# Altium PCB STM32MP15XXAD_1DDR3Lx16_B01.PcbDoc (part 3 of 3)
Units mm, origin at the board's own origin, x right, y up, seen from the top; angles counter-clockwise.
Board outline 86 x 120 mm, 4 copper layers (Top Layer, Signal Layer 1, Signal Layer 2, Bottom Layer), stack 1.571 mm thick; 118 components, 119 nets, 781 pads, 336 vias.
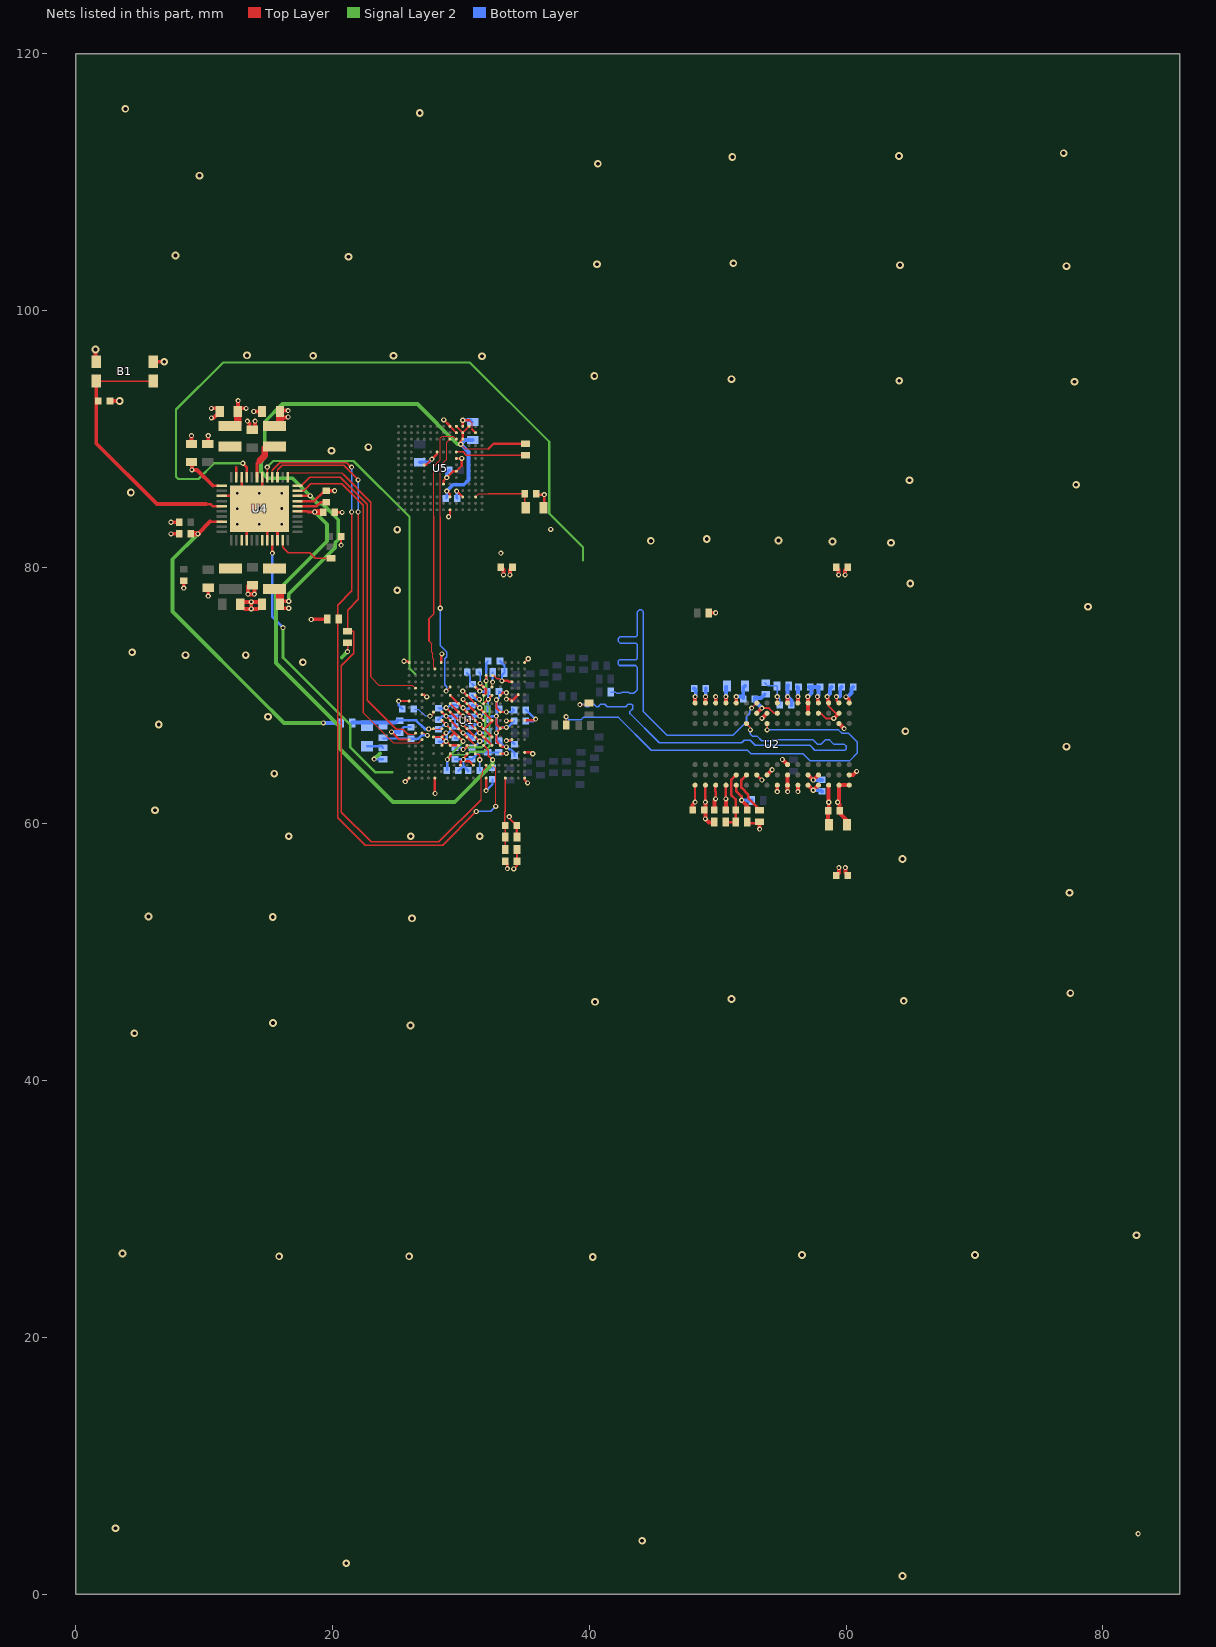
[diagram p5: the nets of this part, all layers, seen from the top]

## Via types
v1: diameter 0.4, hole 0.2, Top Layer to Bottom Layer, tented both sides, 260 vias
v2: diameter 0.6, hole 0.3, Top Layer to Bottom Layer, tented both sides, 74 vias
v3: diameter 0.4, hole 0.2, Top Layer to Signal Layer 1, tented top, 2 vias

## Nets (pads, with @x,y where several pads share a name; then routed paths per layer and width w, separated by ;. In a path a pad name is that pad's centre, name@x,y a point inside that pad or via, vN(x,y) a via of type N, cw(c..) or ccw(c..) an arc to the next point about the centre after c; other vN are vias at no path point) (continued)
GND: B1.1 B1.2 C1.1 C2.1 C3.1 C4.1 C5.1 C6.1 C7.1 C8.1 C9.1 C10.1 C11.1 C12.1 C13.1 C14.1 C15.1 C16.1 C17.1 C18.1 C19.1 C20.1 C21.1 C22.2 C23.1 C24.1 C25.1 C26.1 C27.1 C28.1 C29.1 C30.1 C31.1 C32.1 C33.1 C34.1 C35.1 C36.1 C37.1 C38.1 C39.1 C40.1 C41.1 C42.1 C43.1 C44.1 C45.1 C46.1 C47.1 C48.1 C49.1 C50.1 C51.2 C52.1 C53.1 C54.1 C55.1 C56.1 C57.1 C58.1 C59.1 C78.1 C79.1 C80.1 C81.1 C82.1 C83.1 R1.1 R14.1 R29.1 R31.1 R32.1 R33.1 R36.1 U1.1A6 U1.1B8 U1.1C3 U1.1C5 U1.1C7 U1.1D2 U1.1D4 U1.1D6 U1.1E3 U1.1E5 U1.1E7 U1.1F4 U1.1F6 U1.1G1 U1.1G2 U1.1G5 U1.1G7 U1.1H2 U1.1H3 U1.1H4 U1.1H6 U1.1H8 U1.1J5 U1.1J9 U1.A1 U1.A6 U1.A19 U1.C14 U1.D17 U1.F3 U1.F18 U1.G1 U1.G17 U1.K17 U1.K19 U1.N1 U1.N17 U1.R19 U1.U9 U1.U11 U1.W1 U1.W5 U1.W13 U1.W19 U2.A9 U2.B1 U2.B3 U2.B9 U2.D1 U2.D8 U2.E1 U2.E2 U2.E8 U2.F9 U2.G1 U2.G8 U2.G9 U2.J2 U2.J8 U2.M1 U2.M9 U2.P1 U2.P9 U2.T1 U2.T9 U4.6 U4.10 U4.15 U4.26 U4.30 U4.32 U4.41 U4.ep U5.A6 U5.C4 U5.E7 U5.G5 U5.H10 U5.J5 U5.K8 U5.N2 U5.N5 U5.P4 U5.P6 | length 145.1
  Top Layer w0.09: 30.675,91.45 30.9,91.225 30.9,90.725
  Top Layer w0.12: U1.1C5@30.51,69.34 U1.1C5@30.52,69.33 ; U1.C14@32.475,71.575 32.559,71.575 32.834,71.3 33.025,71.3 33.188,71.138 v1@33.25,71.075 ; U2.M1@51.45,69.425 U2.M1@51.45,69.525 ; v1@55.45,62.435 v1(55.45,62.525) ; U2.E8@57.05,63.825 U2.E8@57.07,63.825
  Top Layer w0.15: U1.A19@34.97,72.58 v1@35.258,72.867 ; v1@48.25,61.695 v1(48.25,61.7) U2.T9@48.25,63.025
  Top Layer w0.175: B1.1@1.55,96.05 B1.1@1.6,96 B1.1@1.6,96.25 ; C18.1@10.3,89.6 C18.1@10.325,89.625 ; C29.1@10.975,92.375 C29.1@11.225,92.125 ; C40.1@13.025,77.3 C40.1@12.825,77.1 13.175,76.75 ; C33.1@13.75,90.7 C33.1@13.975,90.925 ; C31.1@13.775,78.6 C31.1@13.925,78.45 ; 14.175,76.75 C38.1@14.525,77.1 C38.1@14.325,77.3 ; C52.1@20.175,84.275 v1(20.75,84.275) ; v1(20.675,81.725) C51.2@20.675,82.4 ; v1(24.6,67.175) 25.2,66.575 U1.N1@25.975,66.575 ; v1(25.15,69.575) U1.G1@25.975,69.575 ; v1(25.575,72.675) 25.875,72.675 U1.A1@25.975,72.575 ; v1(25.675,63.3) 25.7,63.3 U1.W1@25.975,63.575 ; U1.F3@26.975,70.075 27.175,70.075 v1(27.35,69.9) v1@27.4,69.9 ; U5.H10@27.15,87.975 27.3,87.975 v1(27.75,88.425) 28.15,88.825 U5.K8@28.15,88.975 ; U1.1G1@27.875,66.775 U1.1G2@28.525,66.775 ; v1@27.975,62.425 U1.W5@27.975,63.575 ; U1.A6@28.475,72.575 28.475,73.2 v1(28.525,73.25) ; U1.1H2@28.525,66.125 v1(28.85,66.45) ; U1.1D2@28.575,68.675 v1(28.85,68.4) U1.1E3@29.175,68.075 U1.1F4@29.825,67.425 30.162,67.088 U1.1G5@30.475,66.775 U1.1H6@31.125,66.125 ; U5.E7@28.65,86.475 28.65,86.725 v1(28.9,86.975) 29.4,87.475 U5.G5@29.65,87.475 30.075,87.9 v1(30.075,88.475) U5.J5@29.65,88.475 ; v1(28.675,91.475) 29.15,91 U5.P6@29.15,90.975 U5.N5@29.65,90.475 ; v1(28.85,67.1) U1.1G2@28.525,66.775 ; v1@28.9,66.425 v1@28.9,66.4 ; v1(29.05,83.925) 29.15,84.025 U5.A6@29.15,84.475 ; U1.1C3@29.225,69.325 U1.1D4@29.825,68.725 30.162,68.388 U1.1E5@30.475,68.075 U1.1F6@31.125,67.425 31.462,67.088 U1.1G7@31.775,66.775 U1.1H8@32.425,66.125 ; v1(29.675,85.925) 29.7,85.925 U5.C4@30.15,85.475 ; U1.1H4@29.825,66.125 U1.1H3@29.175,66.125 v1@28.9,66.4 ; U1.U9@29.975,64.575 29.975,64.825 30.188,65.038 30.2,65.05 30.212,65.038 30.367,64.883 30.668,64.883 U1.U11@30.975,64.575 ; U5.P4@30.15,90.948 U5.P4@30.15,90.975 v1(30.15,91.45) 30.675,91.45 ; v1@30.175,65.075 U1.1J5@30.525,65.425 ; v1@30.2,69.625 30.225,69.625 U1.1C5@30.475,69.375 U1.1C5@30.51,69.34 ; U1.1C5@30.52,69.33 30.825,69.025 ; 30.83,69.02 U1.1D6@31.125,68.725 31.462,68.388 U1.1E7@31.775,68.075 ; 30.9,90.725 U5.N2@31.15,90.475 ; U1.1A6@31.15,70.675 v1(31.475,70.35) ; U1.1C7@31.775,69.375 32.125,69.725 v1@32.15,69.75 ; v1(31.975,62.6) U1.W13@31.975,63.575 ; v1(32.15,69.7) v1@32.15,69.75 ; U1.1B8@32.425,70.025 v1@32.15,69.75 ; U1.1J9@33.075,65.475 33.525,65.475 v1(33.55,65.5) ; v1@33.125,81 v1(33.125,81.1) ; v1(33.2,71.15) 33.673,71.15 33.748,71.075 U1.D17@33.975,71.075 ; C9.1@33.475,57.1 33.625,56.95 v1(33.625,56.525) ; v1(33.55,68.025) 33.925,68.025 U1.K17@33.975,68.075 ; v1(33.55,69.725) 33.825,69.725 U1.G17@33.975,69.575 ; v1@33.575,66.575 33.55,66.55 33.575,66.525 33.6,66.5 33.9,66.5 U1.N17@33.975,66.575 ; v1(33.775,60.575) 33.775,60.45 C8.1@34.35,59.875 34.35,59 R36.1@34.375,58.975 ; U1.W19@34.975,63.575 34.975,63.425 v1(35.2,63.2) ; U1.K19@34.975,68.075 35.725,68.075 v1(35.825,68.175) ; C82.1@35.875,85.725 35.95,85.65 v1(36.5,85.65) 36.5,84.675 C83.1@36.45,84.625 ; U1.1G2@28.525,66.775 v1(28.85,66.45) ; v1(28.85,66.45) v1@28.9,66.4 ; v1(28.85,66.45) 28.875,66.425 v1@28.9,66.4
  Top Layer w0.2: U4.15@11.375,85.55 12.6,85.55 U4.ep@13.325,85.55 ; U4.10@12.925,87 12.925,85.95 U4.ep@13.325,85.55 ; U4.26@13.325,82.1 13.325,83.55 U4.ep@14.325,84.55 ; U4.6@14.525,87 14.525,85.75 14.525,84.75 U4.ep@14.325,84.55 ; U4.30@14.925,82.1 U4.ep@14.925,83.95 ; U4.32@15.725,82.1 15.725,83.15 U4.ep@14.925,83.95 ; U4.41@17.275,85.15 18.575,85.15 19.375,85.95 C43.1@19.525,85.95 ; U1.1D2@28.57,68.68 U1.1D2@28.575,68.675 ; U1.G17@33.975,69.575 34.46,70.06 34.46,70.075 U1.F18@34.46,70.08 ; U1.R19@34.97,65.58 34.975,65.58 35.495,65.58 v1(35.6,65.475) ; v1(49.85,61.95) 49.85,62.516 49.82,62.545 49.82,62.995 U2.P9@49.85,63.025 ; U2.M9@51.45,63.025 51.45,62.575 51.875,62.15 v1(51.875,61.85) ; R33.1@52.325,60.045 R31.1@53.13,60.045 ; R31.1@53.04,60.075 53.055,60.06 R31.1@53.13,60.045 ; R31.1@53.285,60.135 53.275,60.125 53.195,60.045 R31.1@53.13,60.045 ; v1(59.25,69.925) 59.272,69.903 59.272,69.603 U2.B1@59.45,69.425 ; U4.ep@13.325,85.55 v1(14.3,84.575) U4.ep@14.325,84.55 ; U4.ep@14.325,84.55 U4.ep@14.925,83.95
  Top Layer w0.25: v3(7.425,82.6) C49.1@8.075,82.6 ; v3(7.425,83.5) C41.1@8.075,83.5 ; v1(8.425,78.375) C32.1@8.425,78.95 ; v1(10.325,77.75) C39.1@10.325,78.4 ; C43.1@19.525,85.95 v1(20.175,85.95)
  Top Layer w0.3: B1.1@1.55,96.05 v2(1.55,96.95) ; C44.1@2.675,92.95 v2(3.425,92.95) ; B1.2@6.05,96 v2(6.9,96) ; C42.1@9.025,89.6 v1(9.025,90.25) ; C18.1@10.325,89.625 v1(10.325,90.25) ; v1(10.575,91.625) 10.725,91.625 C29.1@11.225,92.125 ; v1(10.575,92.375) C29.1@10.975,92.375 ; C40.1@13.025,77.3 v1(13.675,77.3) ; 13.175,76.75 v1(13.675,76.75) ; v1(13.375,91.375) 13.55,91.2 C33.1@13.55,90.925 ; v1(13.425,77.9) C31.1@13.425,78.55 ; v1(13.875,92.125) C34.1@14.525,92.125 ; v1(13.925,77.9) C31.1@13.925,78.45 ; C33.1@13.975,90.925 v1(13.975,91.375) ; 14.175,76.75 v1(13.675,76.75) ; C38.1@14.325,77.3 v1(13.675,77.3) ; C11.1@33.15,80 33.325,79.825 v1(33.325,79.4) ; C27.1@48.05,60.995 C27.1@48.05,61.1 48.05,61.495 v1@48.25,61.695 ; U2.T1@48.25,69.425 v1(48.25,69.925) ; R32.1@49.3,76.45 v1(49.85,76.45) ; C19.1@49.75,61.1 49.75,61.85 v1(49.85,61.95) ; U2.P1@49.85,69.425 v1(49.85,69.925) ; v1(51.45,69.925) U2.M1@51.45,69.425 U2.M1@51.455,69.43 ; v1(51.875,61.85) 52.3,61.425 C28.1@52.3,61.1 ; v1(53.275,59.6) 53.275,60.125 R31.1@53.275,60.15 ; v1(53.45,68.225) U2.J2@53.85,68.625 ; U2.J8@53.85,63.825 v1(54.25,64.225) ; v1(55.45,62.525) U2.G9@55.45,63.025 U2.G8@55.45,63.825 ; U2.G1@55.45,69.425 v1(55.45,69.925) ; v1(56.25,62.525) U2.F9@56.25,63.025 ; v1(57.025,69.925) 57.05,69.9 U2.E1@57.05,69.425 U2.E2@57.05,68.625 ; U2.E8@57.05,63.825 v1(57.45,63.425) U2.D8@57.85,63.825 ; v1@57.775,69.95 57.787,69.938 57.8,69.925 57.8,69.475 U2.D1@57.85,69.425 ; U2.B3@59.45,67.825 v1(59.85,67.425) ; C17.1@59.5,60.995 C17.1@59.5,61.025 ; v1(59.925,79.4) 59.925,79.75 60.162,79.988 C12.1@60.2,80.025 ; v1(59.95,56.6) 59.95,56.225 60.162,56.013 C10.1@60.2,55.975 ; C15.1@60.075,59.95 60.075,60.275 59.5,60.85 C17.1@59.5,61.025 ; U2.A9@60.25,63.025 U2.B9@59.45,63.025 59.45,61.795 v1(59.35,61.695) 59.5,61.545 C17.1@59.5,61.025 ; v1(13.675,76.75) v1(13.675,77.3)
  Top Layer w0.33: v1(13.425,77.9) v1(13.925,77.9)
  Bottom Layer w0.12: v1@51.875,61.875 51.887,61.863 v1@51.925,61.825 ; v1@55.42,69.955 v1(55.45,69.925)
  Bottom Layer w0.175: C2.1@25.075,67.175 C2.1@25.2,67.175 ; C2.1@25.175,67.075 25.191,67.14 C2.1@25.2,67.175 ; v1@25.175,69.575 25.175,69.225 C1.1@25.45,68.95 ; C2.1@25.25,67.125 C2.1@25.2,67.175 ; C50.1@26.125,67.55 25.575,67.55 C2.1@25.2,67.175 ; C36.1@28.25,68.125 28.525,68.4 v1(28.85,68.4) C35.1@29.55,68.4 ; C47.1@28.275,66.425 28.3,66.4 28.85,66.4 v1@28.925,66.4 ; v1@28.825,66.975 v1@28.9,67.05 ; v1@28.9,66.45 v1@28.9,67.05 ; v1@28.925,67.075 v1@28.9,67.05 ; C46.1@29.525,67.625 29.55,67.65 C35.1@29.55,68.35 C35.1@29.55,68.4 ; C4.1@29.55,65.025 29.562,65.038 29.575,65.05 v1@30.2,65.05 ; C46.1@29.55,67.6 29.625,67.6 30.15,67.075 v1@30.175,67.05 ; C46.1@29.55,67.625 29.537,67.612 28.975,67.05 v1@28.9,67.05 ; v1(29.675,85.925) 29.675,85.4 C80.1@29.725,85.35 ; C48.1@29.825,64.15 30.2,64.525 ; v1@30.2,67.05 30.525,67.05 C13.1@30.8,66.775 ; C6.1@30.475,71.75 30.725,71.5 C5.1@30.725,71.075 ; C3.1@30.575,64.15 30.563,64.163 30.2,64.525 ; C81.1@30.775,91.45 C81.1@30.925,91.3 ; C13.1@30.85,66.675 C13.1@30.875,66.7 31.275,67.1 v1(31.475,67.1) 32,67.1 C58.1@32.125,67.225 ; C5.1@30.9,70.9 31.45,70.35 v1(31.475,70.35) ; v1(31.475,68.4) 30.925,68.4 C14.1@30.875,68.35 30.825,68.4 v1(30.175,68.4) 29.552,68.4 C35.1@29.55,68.4 ; v1@31.5,68.35 31.512,68.362 C57.1@32.075,68.925 ; v1@31.5,70.3 32.05,70.3 C53.1@32.075,70.325 C53.1@32.125,70.275 ; v1(31.975,62.6) 32.475,63.1 C7.1@32.475,63.475 ; C57.1@32.075,68.95 C57.1@32.075,68.925 ; C30.1@32.1,65.625 C30.1@32.1,65.575 ; C57.1@32.15,69 C57.1@32.125,68.975 ; C53.1@32.15,70.25 C53.1@32.125,70.275 ; C45.1@33.05,72.7 33.4,72.35 R1.1@33.4,71.8 33.2,71.6 v1(33.2,71.15) ; v1(33.55,65.5) 33.025,65.5 C59.1@32.95,65.575 C30.1@32.1,65.575 ; v1(33.55,66.5) 33.9,66.5 C55.1@34.175,66.225 ; C54.1@35.05,68 35.65,68 v1(35.825,68.175) 35.8,68.175 C56.1@35.075,68.9 ; 30.2,64.525 v1(30.2,65.025) v1@30.2,65.05 ; v1@30.2,65.05 C37.1@30.875,65.05 31.4,65.575 C30.1@32.1,65.575 ; C57.1@32.075,68.925 32.087,68.937 C57.1@32.125,68.975 ; C57.1@32.125,68.975 32.125,69.7 C53.1@32.125,70.275
  Bottom Layer w0.3: v1(24.6,67.175) C2.1@25.2,67.175 ; C79.1@26.8,88.175 27.5,88.175 v1(27.75,88.425) ; v1(28.9,86.975) 28.9,87.35 C78.1@29.1,87.55 ; v1(30.15,91.45) C81.1@30.775,91.45 ; C24.1@48.175,70.55 48.3,70.425 48.3,70 v1@48.25,69.95 ; v1(51.45,69.925) 51.875,69.925 52,69.8 52,70.625 C16.1@52.125,70.75 ; v1@51.925,61.825 R14.1@52.65,61.825 ; R29.1@55.475,70.775 55.45,70.75 v1(55.45,69.925) 55.75,69.625 C26.1@55.75,69.275 C26.1@55.75,69.25 ; v1(57.025,69.925) 57.3,70.2 57.3,70.475 57.15,70.625 57.1,70.675 C23.1@57.2,70.675 C21.1@57.85,70.675 ; v1(57.45,63.425) 57.46,63.435 C22.2@58.13,63.435 ; v1(57.775,69.925) 57.85,70 C21.1@57.85,70.675 ; C21.1@57.86,70.685 C21.1@57.85,70.675 ; C21.1@57.9,70.675 C21.1@57.85,70.675 ; v1@59.39,69.925 59.5,69.925 59.55,69.975 59.55,70.575 C20.1@59.65,70.675
  other v1: 82.75,4.725 28,62.375 30.175,67.1 30.175,69.7 35.25,72.875 37,82.95 12.6,83.35 14.3,83.35 16.05,83.35 12.575,84.55 16.05,84.575 12.6,85.75 14.3,85.75 16.05,85.75
  other v2: 64.4,1.425 21.075,2.425 44.125,4.175 3.1,5.15 40.275,26.275 15.85,26.325 25.975,26.325 56.575,26.425 70.05,26.425 3.65,26.55 82.625,27.975 4.575,43.7 26.075,44.3 15.375,44.5 40.45,46.15 64.5,46.225 51.075,46.375 77.475,46.825 26.2,52.65 15.35,52.75 5.675,52.8 77.4,54.65 64.4,57.275 16.6,59.05 26.1,59.05 31.475,59.05 6.175,61.075 15.475,63.925 77.175,66.025 64.625,67.225 6.475,67.75 14.975,68.35 17.7,72.6 8.55,73.15 13.25,73.15 4.4,73.375 78.85,76.925 25.05,78.2 65,78.725 63.5,81.9 58.95,82 44.8,82.05 54.75,82.075 49.15,82.2 25.05,82.925 4.3,85.825 77.925,86.425 64.95,86.775 19.925,89.075 22.8,89.35 77.8,94.45 64.15,94.525 51.075,94.65 40.4,94.9 31.65,96.425 18.5,96.475 24.75,96.475 13.35,96.5 77.175,103.45 64.2,103.525 40.6,103.6 51.225,103.675 21.25,104.175 7.775,104.275 9.65,110.5 40.675,111.425 51.15,111.95 64.125,112.025 76.95,112.25 26.8,115.375 3.875,115.7
I2C4_SCL: R37.2 U1.U14 U4.4 | length 52.6
  Top Layer w0.09: 15.3,87.54 15.3,87.025 U4.4@15.325,87 ; U1.U14@32.475,64.575 32.72,64.33 v1@32.72,61.425
  Top Layer w0.1: 15.3,87.54 15.885,88.125 21.1,88.125 21.425,87.8 v1(21.5,87.8) ; v1(21.5,84.3) 21.5,78.15 20.4,77.05 20.4,75.95 20.4,60.5 22.55,58.35 28.575,58.35 v1(31.2,60.975)
  Bottom Layer w0.1: v1(21.5,84.3) v1(21.5,87.8) ; v1(31.2,60.975) 32.325,60.975 v1(32.725,61.375)
I2C4_SDA: R38.2 U1.U13 U4.3 | length 50.6
  Top Layer w0.09: U4.3@15.725,87 15.725,87.575 ; 31.575,61.9 31.575,63.762 31.72,63.907 31.72,64.166 31.975,64.421 U1.U13@31.975,64.575
  Top Layer w0.1: 15.725,87.575 16.075,87.925 20.875,87.925 v1(22,86.8) ; v1@22.025,84.275 22.025,77.5 21.175,76.65 R38.2@21.175,75 21.675,75 21.675,73.3 20.7,72.325 20.7,60.925 23.025,58.6 28.275,58.6 31.575,61.9
  Bottom Layer w0.1: v1(22,84.3) v1(22,86.8)
NetB1_3: B1.3 B1.4 C44.2 U4.17 | length 21.5
  Top Layer w0.1: B1.3@1.325,94.775 B1.3@1.6,94.5 B1.4@6.05,94.5
  Top Layer w0.2: 10.125,84.9 10.525,84.9 10.675,84.75 U4.17@11.375,84.75
  Top Layer w0.3: B1.3@1.6,94.45 1.6,92.95 1.6,89.65 6.325,84.925 10.15,84.925
NetC1_2: C1.2 U1.1D1 | length 1.9
  Top Layer w0.09: v1(27.6,68.4) 27.65,68.4 27.925,68.675 U1.1D1@27.925,68.65
  Bottom Layer w0.09: C1.2@26.375,68.95 26.7,68.95 27.225,68.425 27.55,68.425 27.587,68.388 v1@27.6,68.375
NetC2_2: C2.2 L5.2 R41.1 R42.2 U1.1F1 U1.1F2 | length 7.4
  Top Layer w0.09: v1@27.5,67.375 27.875,67.375 28.525,67.375 U1.1F2@28.575,67.375
  Bottom Layer w0.2: C2.2@25.075,68.075 25.25,68.075 26.525,68.075 27.2,67.4 v1(27.5,67.4)
  Bottom Layer w0.3: R42.2@21.55,67.9 22.7,67.9 23.925,67.9 24.9,67.9 C2.2@25.075,68.075
NetC3_2: C3.2 U1.1J6 | length 1.7
  Top Layer w0.09: v1@31.5,65 v1@31.5,65.1
  Top Layer w0.1: U1.1J6@31.175,65.425 31.4,65.425 31.475,65.35 v1(31.475,65) v1@31.5,65
  Bottom Layer w0.1: C3.2@31.475,64.175 v1(31.475,65)
  Bottom Layer w0.175: C3.2@31.5,64.2 C3.2@31.525,64.175
NetC6_2: C6.2 U1.1A7 U1.1B7 | length 2.1
  Top Layer w0.2: v1(31.5,70.95) U1.1A7@31.775,70.675 31.95,70.5 31.95,70.2 U1.1B7@31.775,70.025
  Bottom Layer w0.1: C6.2@31.4,71.85 31.5,71.75 v1(31.5,70.95)
NetC8_2: C8.2 R35.1 R36.2 U1.W16 | length 5.6
  Top Layer w0.1: R35.1@33.475,58 33.45,58.025 33.45,58.975 C8.2@33.45,59.875 33.425,59.9 33.425,60.95 33.475,61 U1.W16@33.475,63.575
NetC26_2: C26.2 R28.1 R29.2 U2.H1 | length 3.1
  Top Layer w0.12: U2.H1@54.65,69.39 U2.H1@54.65,69.425 v1@54.65,69.905
  Bottom Layer w0.1: R29.2@54.575,70.75 54.6,70.725 R29.2@54.65,70.675
  Bottom Layer w0.12: R28.1@53.675,71 53.712,70.963 53.925,70.75 R29.2@54.575,70.75 ; R29.2@54.65,70.675 v1(54.65,69.925) 54.85,69.725 C26.2@54.85,69.275
NetC28_2: C28.2 R30.1 R33.2 U2.M8 | length 4.8
  Top Layer w0.1: R30.1@50.625,60.15 R30.1@50.65,60.15 ; R33.2@51.41,60.165 R33.2@51.425,60.15
  Top Layer w0.12: 51.413,61.913 51.425,61.9
  Top Layer w0.2: R30.1@50.65,60.15 R33.2@51.425,60.15 ; R33.2@51.41,60.165 C28.2@51.41,61.1 51.425,61.115 51.425,61.9 ; 51.413,61.913 51.05,62.275 51.05,63.425 U2.M8@51.45,63.825
NetC43_2: C43.2 U4.40 | length 2.4
  Top Layer w0.2: U4.40@17.275,84.75 18.775,84.75 19.075,85.05 C43.2@19.525,85.05
NetC82_2: C82.2 C83.2 U5.C2 | length 5.1
  Top Layer w0.09: U5.C2@31.15,85.475 31.4,85.725 32.15,85.725
  Top Layer w0.1: 32.15,85.725 C82.2@34.975,85.725 34.975,84.7 C83.2@35.05,84.625
NetL1_1: L1.1 U4.7 | length 3.2
  Top Layer w0.2: U4.7@14.125,87 14.125,88.1 14.325,88.3
  Top Layer w0.5: 14.325,88.3 14.725,88.7 14.725,89.3 14.825,89.4 L1.1@15.325,89.4
NetL2_1: L2.1 U4.11 | length 0.8
  Top Layer w0.2: U4.11@12.525,87 12.525,87.8
NetL3_1: L3.1 U4.29
NetL4_1: L4.1 U4.25
NetL5_1: L5.1 R39.2 | length 1.3
  Bottom Layer w0.2: L5.1@22.7,66.05 23.825,66.05 R39.2@23.925,65.95
NetR1_2: R1.2 U1.1A8 | length 1.2
  Top Layer w0.09: U1.1A8@32.425,70.675 32.425,71 v1(32.475,71.05)
  Bottom Layer w0.1: R1.2@32.475,71.775 R1.2@32.5,71.8
  Bottom Layer w0.175: v1(32.475,71.05) R1.2@32.475,71.775
NetR31_2: R31.2 U2.L8 | length 3.5
  Top Layer w0.2: U2.L8@52.25,63.825 51.85,63.425 51.85,62.825 52.4,62.275 52.4,61.995 53.26,61.135 R31.2@53.26,61.075 R31.2@53.26,61.055
NetR40_1: R40.1 U5.K5 | length 5.5
  Top Layer w0.1: U5.K5@29.65,88.975 30.175,88.975 30.42,88.73 31.98,88.73 31.985,88.725 R40.1@35.025,88.725
NetR43_1: R43.1 U4.33 | length 4.7
  Top Layer w0.1: U4.33@16.125,82.1 16.125,81.55 16.55,81.125 18.25,81.125 18.675,80.7 R43.1@19.9,80.7
NRST: U1.E2 U4.1 | length 25.2
  Top Layer w0.09: U4.1@16.525,87 16.525,87.35 20.725,87.35 20.85,87.225 ; 23,71.45 23.625,70.825 26.225,70.825 U1.E2@26.475,70.575
  Top Layer w0.1: 20.85,87.225 23,85.075 23,71.45
ODT: R27.2 U2.K1 | length 33.2
  Top Layer w0.12: v1(52.65,69.025) U2.K1@53.05,69.425
  Bottom Layer w0.12: R27.2@41.675,70.275 42.05,70.275 42.155,70.17 42.445,70.17 42.55,70.275 43.05,70.275 43.15,70.175 43.475,70.175 43.725,70.425 43.725,72.225 43.605,72.345 42.355,72.345 42.245,72.455 42.245,72.695 42.35,72.8 43.65,72.8 43.725,72.875 43.725,74 43.63,74.095 42.4,74.095 42.245,74.25 42.245,74.42 42.4,74.575 43.625,74.575 43.725,74.675 43.725,76.5 43.9,76.675 44.075,76.675 44.225,76.525 44.225,68.75 46,66.975 46.07,66.905 51.2,66.905 52.14,67.845 52.14,67.851 52.25,67.961 52.25,68.334 52.5,68.584 52.5,68.814 52.65,68.964 v1(52.65,69.025)
PA0_WKUP: U1.N3 U4.43 | length 27.8
  Top Layer w0.09: 22.4,68.675 24.75,66.325 26.725,66.325 U1.N3@26.975,66.575
  Top Layer w0.1: 17.775,85.95 18.325,86.5 20.725,86.5 22.4,84.825 22.4,68.675
  Top Layer w0.12: U4.43@17.275,85.95 17.775,85.95
PWR_ON: U1.M2 U4.44 | length 26.4
  Top Layer w0.09: 26.05,66.99 26.39,66.99 U1.M2@26.475,67.075
  Top Layer w0.1: U4.44@17.575,86.35 18.225,87 20.625,87 22.725,84.9 22.725,69.625 24.957,67.392 25.465,67.392 25.853,67.005 26.05,67.005
RASN: R22.2 U2.J3 | length 34
  Top Layer w0.09: v1(38.2,68.35) 38.2,67.7 38.212,67.688 R22.2@38.225,67.675
  Top Layer w0.12: v1(53.85,67.325) U2.J3@53.85,67.825
  Bottom Layer w0.12: v1(38.2,68.35) 38.44,68.11 39.355,68.11 39.545,68.3 42.281,68.3 44.836,65.745 52.32,65.745 52.58,65.485 56.64,65.485 57.215,64.91 60.273,64.91 60.865,65.502 60.865,66.404 60.199,67.07 60.004,67.07 59.999,67.065 59.685,67.065 59.425,67.325 v1(53.85,67.325) v1@53.875,67.35
SDMMC2_CK: U1.1A3 U5.M6 | length 20.8
  Top Layer w0.09: 28.4,83.925 28.4,87.9 28.9,88.4 28.9,89.725 U5.M6@29.15,89.975 ; v1(28.85,70.35) U1.1A3@29.175,70.675 ; v1@28.888,70.287 v1@28.9,70.3
  Top Layer w0.13: v1(28.4,76.8) 28.4,83.925
  Bottom Layer w0.1: 28.75,71.7 28.75,70.853 28.9,70.703 28.9,70.35 v1@28.9,70.275
  Bottom Layer w0.13: v1(28.4,76.8) 28.4,73.9 28.9,73.4 28.9,73.025 28.75,72.875 28.75,71.7
SDMMC2_CMD: U1.B5 U5.M5 | length 20
  Top Layer w0.09: 27.525,74.25 27.753,74.022 27.753,73.378 27.822,73.31 27.822,72.914 27.89,72.845 27.89,72.21 U1.B5@27.975,72.125 ; 27.9,83.975 27.9,87.875 28.4,88.375 28.4,90.064 28.551,90.215 29.41,90.215 U5.M5@29.65,89.975 ; U1.B5@27.975,72.075 U1.B5@27.975,72.125 ; U1.B5@27.975,72.145 U1.B5@27.975,72.125
  Top Layer w0.13: 27.525,74.25 27.525,75.975 27.9,76.35 27.9,83.975
VDD: C38.2 C45.2 C46.2 C47.2 C48.2 C80.2 C81.2 L3.2 R37.1 R38.1 R39.1 R40.2 U1.1E2 U1.1F3 U1.1G3 U1.1G4 U1.1J3 U1.C13 U4.31 U4.42 U5.C6 U5.M4 U5.N4 U5.P3 U5.P5 | length 102.2
  Top Layer w0.09: C38.2@16.175,77.35 C38.2@15.925,77.1 C38.2@16.225,76.8 ; v1(18.35,75.925) v1@18.375,75.95 ; v1(30,89.575) 30.35,89.225 32.15,89.225
  Top Layer w0.1: v1(21.175,73.425) R38.1@21.175,74.1
  Top Layer w0.175: U1.1E2@28.525,68.075 v1(28.85,67.75) U1.1F3@29.175,67.425 29.5,67.1 ; v1(28.9,85.925) 29.15,85.675 U5.C6@29.15,85.475 ; v1(28.95,65.025) 29.225,65.3 U1.1J3@29.225,65.425 ; U1.1G3@29.175,66.775 29.5,67.1 ; U5.P5@29.65,90.975 U5.N4@30.15,90.475 ; v1(30,89.575) 30,89.825 U5.M4@30.15,89.975 U5.N4@30.15,90.475 ; v1@30.2,66.42 30.172,66.447 29.845,66.775 U1.1G4@29.825,66.775 29.5,67.1 ; U5.P3@30.65,90.975 U5.N4@30.15,90.475 ; v1(31.975,71.15) U1.C13@31.975,71.575 ; 32.15,89.225 32.55,89.625 R40.2@35.025,89.625
  Top Layer w0.2: v1(15.325,81.1) U4.31@15.325,82.1 ; U4.42@17.275,85.55 v1(18.275,85.55)
  Top Layer w0.3: C38.2@16.175,77.35 v1(16.6,77.35) ; C38.2@16.225,76.8 v1(16.6,76.8) ; v1@18.375,75.95 R37.1@19.6,75.95
  Top Layer w0.6: C38.2@15.925,77.1 L3.2@15.925,78.3
  Signal Layer 2 w0.09: 31.803,69.948 31.803,69.56 32.225,69.137 32.225,69
  Signal Layer 2 w0.1: v1(28.95,65.025) v1@28.975,65.05 ; 29.2,65.4 30.525,65.4
  Signal Layer 2 w0.175: v1@28.9,67.7 30.162,66.437 v1@30.2,66.4 ; v1@28.975,65.025 28.975,65.05 28.975,65.175 29.2,65.4 v1@30.2,66.4 ; v1@30.25,66.35 v1@30.2,66.4 ; 30.525,65.425 30.73,65.63 31.805,65.63 32.225,66.05 32.225,69 ; 31.803,69.948 31.975,70.12 v1(31.975,71.15)
  Signal Layer 2 w0.2: v1(16.15,75.3) 16.15,72.95 21.4,67.7 21.4,65.975 23.35,64.025 24.675,64.025
  Signal Layer 2 w0.3: v1(16.6,77.35) 16.6,77.914 20.225,81.539 20.225,81.911 20.45,82.136 20.45,83.7 19.175,84.975 18.85,84.975 v1(18.275,85.55) 16.9,86.925 14.95,86.925 14.425,87.45 14.425,88.2 14.725,88.5 14.725,91.325 16.1,92.7 26.625,92.7 29.75,89.575 v1(30,89.575) ; 20.725,72.975 v1(21.175,73.425) ; v1(23.25,65.05) 23.7,65.5
  Bottom Layer w0.1: C80.2@28.825,85.35 C80.2@28.9,85.425 ; C45.2@31.975,72.525 C45.2@32.15,72.7
  Bottom Layer w0.175: v1(23.25,65.05) R39.1@23.925,65.05 ; C47.2@28.3,67.375 28.625,67.7 28.85,67.7 v1@28.9,67.7 ; C80.2@28.9,85.425 v1(28.9,85.925) ; C48.2@28.925,64.2 28.95,64.225 v1(28.95,65.025) ; C46.2@29.55,66.675 29.925,66.675 30.162,66.437 v1@30.2,66.4 ; v1(31.975,71.15) C45.2@31.975,72.525
  Bottom Layer w0.2: v1(15.325,81.1) 15.325,76.125 v1(16.15,75.3)
  Bottom Layer w0.3: v1(28.9,85.925) 29.4,86.425 30.225,86.425 30.6,86.8 30.6,88.975 v1(30,89.575) 30.325,89.9 C81.2@30.925,89.9
  other v1: 30.175,66.45
VDD_CORE: C13.2 C14.2 C30.2 C34.2 C35.2 C36.2 C37.2 L1.2 U1.1B3 U1.1B5 U1.1C4 U1.1C6 U1.1D3 U1.1D5 U1.1D7 U1.1E4 U1.1E6 U1.1E8 U1.1F5 U1.1F7 U1.1G6 U1.1G8 U4.5 | length 48.1
  Top Layer w0.15: U4.5@14.925,87 v1(14.925,87.8)
  Top Layer w0.175: C34.2@15.925,92.125 C34.2@16,92.2 ; v1@16.5,91.65 v1(16.55,91.7) ; v1@28.9,69 U1.1D3@29.175,68.725 U1.1E4@29.825,68.075 30.162,67.738 U1.1F5@30.475,67.425 U1.1G6@31.125,66.775 31.175,66.725 v1@31.462,66.437 ; U1.1B3@29.225,69.975 U1.1C4@29.825,69.375 30.162,69.038 U1.1D5@30.475,68.725 U1.1E6@31.125,68.075 31.462,67.738 U1.1F7@31.775,67.425 U1.1F7@31.825,67.375 ; v1@30.188,70.313 U1.1B5@30.475,70.025 U1.1C6@31.125,69.375 31.462,69.038 U1.1D7@31.775,68.725 31.825,68.675 U1.1E8@32.425,68.075 32.475,68.025 U1.1F7@31.825,67.375 ; U1.1G8@32.425,66.775 U1.1F7@31.825,67.375
  Top Layer w0.3: 15.925,91.65 v1@16.5,91.65 ; C34.2@16,92.2 v1(16.55,92.2)
  Top Layer w0.6: L1.2@15.325,91 L1.2@15.475,91 15.725,91 15.925,91.2 15.925,91.65 C34.2@15.925,92.1
  Signal Layer 2 w0.175: v1(14.925,87.8) 15.4,88.275 21.65,88.275 26,83.925 26,72.125 26.45,71.675
  Bottom Layer w0.175: C36.2@28.3,69.025 28.325,69 28.85,69 28.9,69 29.15,69.25 C35.2@29.55,69.25 29.925,69.25 30.15,69.025 v1@30.225,68.95 ; v1(30.175,67.75) 30.725,67.75 C13.2@30.875,67.6 31.025,67.75 v1(31.475,67.75) ; v1@30.2,68.975 30.625,68.975 30.887,69.237 C14.2@30.9,69.25 ; C37.2@30.875,65.95 31.025,65.95 31.475,66.4 v1(31.475,66.45) ; C14.2@30.875,69.25 C14.2@30.9,69.25 ; v1@31.475,66.475 C30.2@32.1,66.475 ; v1@31.525,69.025 31.487,69.063 31.3,69.25 C14.2@30.9,69.25
  other v1: 28.85,69.05 30.175,69.05 31.475,69.05 30.15,70.35
VDD_DDR: C9.2 C10.2 C11.2 C12.2 C15.2 C16.2 C17.2 C19.2 C20.2 C21.2 C22.1 C23.2 C24.2 C25.2 C27.2 C29.2 C42.2 C53.2 C54.2 C55.2 C56.2 C57.2 C58.2 C59.2 L2.2 R28.2 R30.2 R35.2 U1.1B9 U1.1D9 U1.1F9 U1.1H9 U2.A1 U2.A8 U2.B2 U2.C1 U2.C9 U2.D2 U2.D9 U2.E9 U2.F1 U2.G7 U2.H2 U2.H9 U2.K2 U2.K8 U2.N1 U2.N9 U2.R1 U2.R9 U4.9 U4.13 | length 110
  Top Layer w0.09: v1@33.525,66.075 v1@33.575,66.025
  Top Layer w0.12: U4.13@11.075,86.35 U4.13@11.375,86.35 ; v1@50.625,61.975 v1@50.65,62 ; 54.4,68.625 U2.H2@54.65,68.625 ; U2.A8@60.25,63.825 60.445,63.825 60.515,63.895
  Top Layer w0.15: v1(53.45,69.025) 54,69.025 54.4,68.625 U2.H2@54.65,68.625 ; U2.D2@57.85,68.625 58.03,68.625 58.43,68.225 v1(59.05,68.225) ; U2.C1@58.65,69.425 58.65,69.175 59.2,68.625 U2.B2@59.45,68.625
  Top Layer w0.153: v1(59.05,68.225) U2.B2@59.325,68.5
  Top Layer w0.175: v1@9.025,87.6 v1(9.05,87.575) ; C42.2@9.025,88.2 C42.2@9.05,88.175 ; C29.2@12.625,92.125 12.65,92.15 C29.2@12.875,92.375 ; v1(32.775,68.4) 32.775,67.725 U1.1F9@33.075,67.425 ; v1(32.775,69.675) 32.775,69.025 U1.1D9@33.075,68.725 33.5,68.725 33.525,68.7 v1(33.55,68.725) ; U1.1B9@33.075,70.025 33.275,70.225 v1(33.55,70.225) ; v1(33.55,67.525) 33.175,67.525 U1.1F9@33.075,67.425 ; v1@33.575,66.025 33.55,66.025 33.175,66.025 U1.1H9@33.075,66.125 32.775,66.425 v1(32.775,67.1) 32.775,67.125 U1.1F9@33.075,67.425 ; v1(34.125,56.5) 34.375,56.75 C9.2@34.375,57.1 R35.2@34.375,58
  Top Layer w0.2: 10.675,86.35 U4.13@11.075,86.35 ; v1(13.025,88.1) 13.325,87.8 U4.9@13.325,87 ; v1@49.05,61.695 v1(49.05,61.7) U2.R9@49.05,63.025 ; v1@50.65,62 U2.N9@50.65,63.025 ; U2.K8@53.05,63.825 v1(53.45,63.425)
  Top Layer w0.3: C42.2@9.05,88.175 v1(9.05,87.575) 9.45,87.575 10.675,86.35 ; C29.2@12.65,92.15 v1(12.65,92.975) ; C29.2@12.875,92.375 v1(13.275,92.375) ; v1(33.825,79.4) 33.825,79.8 C11.2@34.025,80 ; v1@49.05,61.695 49.05,61.1 v1(49.05,60.4) 49.325,60.125 49.75,60.125 R30.2@49.775,60.125 ; U2.R1@49.05,69.425 v1@49.05,69.925 ; C19.2@50.64,60.995 C19.2@50.65,61.005 ; C19.2@50.65,61.1 v1(50.65,61.95) ; U2.N9@50.65,63.025 U2.N9@50.68,62.995 ; U2.N1@50.65,69.425 v1(50.65,69.925) v1@50.65,69.95 ; U2.K2@53.05,68.615 U2.K2@53.05,68.625 v1(53.45,69.025) ; v1(54.65,62.525) U2.H9@54.65,63.025 ; v1(55.05,65.025) U2.G7@55.45,64.625 ; U2.F1@56.25,69.425 v1(56.25,69.925) ; U2.E9@57.05,63.025 v1(57.45,62.625) U2.D9@57.85,63.025 ; v1(58.525,69.925) 58.575,69.875 58.575,69.593 58.593,69.593 58.65,69.537 U2.C1@58.65,69.425 ; C17.2@58.6,61.025 C17.2@58.6,60.995 ; C15.2@58.65,59.975 58.6,60.025 C17.2@58.6,60.995 ; U2.C9@58.65,63.025 58.65,61.705 v1(58.66,61.695) 58.66,61.055 58.615,61.01 C17.2@58.6,60.995 ; v1(59.05,68.225) U2.B2@59.45,68.625 ; C12.2@59.225,80.025 C12.2@59.25,80 59.425,79.825 v1(59.425,79.4) ; C10.2@59.25,55.975 59.263,55.988 59.45,56.175 v1(59.45,56.6) ; v1(60,69.9) 60.25,69.65 U2.A1@60.25,69.425 ; U2.A8@60.25,63.825 60.55,63.825 v1(60.825,64.1)
  Top Layer w0.6: L2.2@12.025,91 12.525,91 12.625,91.1 C29.2@12.625,92.1
  Signal Layer 2 w0.175: v1(13.025,88.1) 10.8,88.1 9.575,86.875 8,86.875 7.825,87.05 7.825,92.275 11.5,95.95 30.7,95.95 36.888,89.762 36.888,84.187 39.525,81.55 39.525,80.525
  Bottom Layer w0.175: C58.2@32.125,68.125 32.4,68.4 v1(32.775,68.4) ; v1(33.55,70.225) 33.075,70.225 C53.2@32.975,70.325 32.975,69.825 32.8,69.65 C57.2@32.8,69.125 ; C56.2@34.025,68.975 C56.2@34.137,68.863 ; C54.2@34.15,68.025 33.65,67.525 v1(33.55,67.525) 32.8,67.525 ; C56.2@34.15,68.85 C56.2@34.138,68.863 ; C56.2@34.15,68.875 C56.2@34.138,68.863 ; C55.2@34.175,65.325 34.175,65.552 33.925,65.802 33.796,65.802 33.598,66 v1(33.55,66) 33.425,66 C59.2@32.95,66.475 32.8,66.625 32.8,67.1 32.8,67.525 ; C16.2@50.65,70.675 C16.2@50.725,70.75 ; 32.8,67.525 32.8,68.4 32.8,68.95 C57.2@32.8,69.125 ; C57.2@32.8,69.125 C57.2@32.975,68.95 33.2,68.725 v1(33.55,68.725) 34,68.725 C56.2@34.138,68.863
  Bottom Layer w0.3: v1@49.075,69.95 C24.2@49.075,70.55 ; v1(50.65,69.925) C16.2@50.65,70.675 ; v1@53.5,69.025 v1(53.45,69.025) 52.9,69.575 C25.2@52.9,69.725 52.9,69.8 53.375,69.8 R28.2@53.675,70.1 ; C23.2@56.2,70.675 56.25,70.625 v1(56.25,69.925) ; v1(57.45,62.625) 58.04,62.625 C22.1@58.13,62.535 ; v1(58.525,69.925) 58.76,70.16 58.76,70.56 C21.2@58.875,70.675 ; v1@60.15,69.925 60.44,70.215 60.44,70.565 C20.2@60.55,70.675
  other v1: 49.055,69.925
VDD_USB: C7.2 C52.2 U1.1H7 U4.39 | length 41.7
  Top Layer w0.1: U1.1H7@31.775,66.125 32.15,65.75 32.15,65.325 v1(32.475,65)
  Top Layer w0.2: U4.39@17.275,84.35 18.075,84.35 18.125,84.3 v1(18.625,84.3)
  Top Layer w0.45: v1(18.625,84.3) C52.2@19.175,84.3
  Signal Layer 2 w0.3: v1(18.625,84.3) 19.575,83.35 19.575,82.025 15.6,78.05 15.6,72.55 20.525,67.625 20.525,65.925 24.725,61.725 29.525,61.725 32.475,64.675 v1(32.475,65)
  Bottom Layer w0.175: C7.2@32.475,64.375 v1(32.475,65)
VDDA: C49.2 R42.1 U4.20 | length 26.4
  Top Layer w0.2: 10.475,83.55 U4.20@11.375,83.55
  Top Layer w0.3: v1(9.525,82.6) 10.475,83.55
  Top Layer w0.45: C49.2@8.975,82.6 v1(9.525,82.6)
  Signal Layer 2 w0.3: v1(9.525,82.6) 7.55,80.625 7.55,76.55 15.2,68.9 15.203,68.9 15.525,68.578 15.525,68.575 16.225,67.875 v1(19.3,67.875)
  Bottom Layer w0.3: v1(19.3,67.875) R42.1@20.65,67.875
VDDA_1V8: C4.2 C5.2 U1.1B6 U1.1H5 | length 7.9
  Top Layer w0.09: v1(31.45,69.7) v1@31.525,69.625
  Top Layer w0.175: U1.1B6@31.125,70.025 v1(31.45,69.7)
  Top Layer w0.2: v1@30.21,65.765 30.52,66.075 U1.1H5@30.52,66.08
  Signal Layer 2 w0.09: v1(31.45,69.7) 31.45,69.563 31.9,69.113 31.9,69.1
  Signal Layer 2 w0.1: v1@30.2,65.775 v1@30.225,65.775
  Signal Layer 2 w0.175: v1@30.225,65.775 30.425,65.975 31.625,65.975 31.9,66.25 31.9,69.1
  Bottom Layer w0.175: C4.2@29.55,65.95 29.975,65.95 v1@30.15,65.775 ; C5.2@30.9,70 31.2,69.7 v1(31.45,69.7)
  other v1: 30.175,65.8
VREF+: C50.2 R41.2 U1.M3 | length 4.1
  Top Layer w0.09: U1.M3@26.975,67.05 U1.M3@26.975,67.075 27.2,67.075 v1@27.375,66.9
  Top Layer w0.1: U1.M3@26.975,67.025 U1.M3@26.975,67.05
  Bottom Layer w0.1: R41.2@23.925,66.725 R41.2@24,66.65
  Bottom Layer w0.175: R41.2@24,66.65 C50.2@26.125,66.65
  Bottom Layer w0.2: C50.2@26.125,66.65 26.7,66.65 26.95,66.9 v1(27.4,66.9)
WEN: R26.2 U2.L3 | length 33.8
  Top Layer w0.09: v1(39.275,69.3) 39.85,69.3 R26.2@39.975,69.425
  Top Layer w0.12: U2.L3@52.25,67.825 52.55,67.525 v1(52.55,67.325)
  Bottom Layer w0.12: v1(39.275,69.3) 39.3,69.325 39.575,69.325 39.76,69.14 39.925,69.14 40.11,69.325 40.25,69.325 40.375,69.325 40.56,69.14 40.7,69.14 40.885,69.325 40.975,69.325 41.215,69.325 41.4,69.14 42.84,69.14 43.025,69.325 43.3,69.325 43.385,69.24 43.385,68.975 43.175,68.765 43.175,68.6 45.415,66.36 ; 45.375,66.4 45.45,66.325 51.44,66.325 51.445,66.33 51.88,66.33 52.075,66.525 52.544,66.525 52.859,66.21 ; v1(52.55,67.325) 52.55,67 52.7,66.85 53.075,66.85 53.44,66.485 54.198,66.485 54.263,66.55 57.45,66.55 57.8,66.2 58.025,66.2 58.375,66.55 58.725,66.55 59.075,66.2 59.875,66.2 60.025,66.05 60.025,65.85 59.925,65.75 57.575,65.75 57.2,66.125 52.93,66.125 52.852,66.203
pads on no net: U1.1A1 U1.1A2 U1.1A5 U1.1B1 U1.1B2 U1.1B4 U1.1C1 U1.1C2 U1.1C8 U1.1D8 U1.1E1 U1.1F8 U1.1H1 U1.1J1 U1.1J2 U1.1J4 U1.1J7 U1.1J8 U1.A2 U1.A3 U1.A4 U1.A7 U1.A9 U1.A10 U1.A12 U1.A13 U1.A15 U1.A16 U1.B1 U1.B2 U1.B3 U1.B4 U1.B9 U1.B10 U1.B11 U1.B12 U1.B13 U1.B14 U1.B15 U1.C1 U1.C2 U1.C3 U1.C4 U1.C5 U1.C6 U1.C11 U1.C12 U1.C15 U1.D1 U1.D2 U1.D3 U1.E1 U1.E3 U1.F2 U1.G2 U1.G3 U1.H1 U1.H2 U1.H3 U1.J2 U1.J3 U1.K1 U1.K2 U1.K3 U1.L1 U1.L2 U1.L3 U1.N2 U1.P1 U1.P2 U1.P3 U1.R2 U1.R3 U1.T1 U1.T2 U1.T3 U1.U1 U1.U2 U1.U3 U1.U4 U1.U5 U1.U6 U1.U7 U1.U8 U1.U10 U1.U12 U1.U15 U1.U16 U1.V1 U1.V2 U1.V3 U1.V4 U1.V5 U1.V6 U1.V7 U1.V8 U1.V9 U1.V10 U1.V11 U1.V12 U1.V13 U1.V14 U1.V15 U1.V16 U1.W2 U1.W3 U1.W4 U1.W7 U1.W8 U1.W10 U1.W11 U1.W14 U2.J1 U2.J9 U2.L1 U2.L9 U4.2 U4.14 U4.16 U4.18 U4.21 U4.23 U4.34 U4.35 U4.38 U5.A1 U5.A2 U5.A7 U5.A8 U5.A9 U5.A10 U5.A11 U5.A12 U5.A13 U5.A14 U5.B1 U5.B7 U5.B8 U5.B9 U5.B10 U5.B11 U5.B12 U5.B13 U5.B14 U5.C1 U5.C3 U5.C5 U5.C7 U5.C8 U5.C9 U5.C10 U5.C11 U5.C12 U5.C13 U5.C14 U5.D1 U5.D2 U5.D3 U5.D4 U5.D12 U5.D13 U5.D14 U5.E1 U5.E2 U5.E3 U5.E5 U5.E8 U5.E9 U5.E10 U5.E12 U5.E13 U5.E14 U5.F1 U5.F2 U5.F3 U5.F10 U5.F12 U5.F13 U5.F14 U5.G1 U5.G2 U5.G3 U5.G10 U5.G12 U5.G13 U5.G14 U5.H1 U5.H2 U5.H3 U5.H5 U5.H12 U5.H13 U5.H14 U5.J1 U5.J2 U5.J3 U5.J12 U5.J13 U5.J14 U5.K1 U5.K2 U5.K3 U5.K6 U5.K7 U5.K10 U5.K12 U5.K13 U5.K14 U5.L1 U5.L2 U5.L3 U5.L12 U5.L13 U5.L14 U5.M1 U5.M2 U5.M3 U5.M7 U5.M8 U5.M9 U5.M10 U5.M11 U5.M12 U5.M13 U5.M14 U5.N1 U5.N3 U5.N6 U5.N7 U5.N8 U5.N9 U5.N10 U5.N11 U5.N12 U5.N13 U5.N14 U5.P1 U5.P2 U5.P7 U5.P8 U5.P9 U5.P10 U5.P11 U5.P12 U5.P13 U5.P14
copper on no net: | length 133.2
  Top Layer w0.09: 25.475,68.075 25.975,68.075 ; 25.48,64.33 26.076,64.33 26.321,64.575 26.475,64.575 ; 25.5,67.825 26.725,67.825 26.975,68.075 ; 25.5,72.075 25.975,72.075 ; 25.525,66.075 25.975,66.075 ; 25.525,70.575 25.975,70.575 ; 25.525,71.575 25.975,71.575 ; 25.55,69.075 25.975,69.075 ; 25.55,71.075 25.975,71.075 ; 25.57,65.83 26.076,65.83 26.161,65.914 26.321,66.075 26.475,66.075 ; 25.575,64.075 25.975,64.075 ; 25.58,63.83 26.076,63.83 26.22,63.974 26.22,64.166 26.379,64.325 26.725,64.325 26.975,64.575 ; 25.58,64.83 26.08,64.83 26.175,64.925 26.325,65.075 26.475,65.075 ; 25.6,64.575 25.975,64.575 ; 25.6,65.075 25.975,65.075 ; 25.6,67.575 25.975,67.575 ; 25.625,71.325 26.225,71.325 26.475,71.075 ; 25.63,71.82 26.08,71.82 26.325,71.575 26.475,71.575 ; 25.745,68.32 26.23,68.32 26.475,68.075 ; 25.78,72.32 26.08,72.32 26.225,72.175 26.225,71.975 26.375,71.825 26.725,71.825 26.975,71.575 ; 25.805,66.82 26.23,66.82 26.475,66.575 ; 25.825,69.325 26.725,69.325 26.975,69.075 ; 25.9,65.32 26.73,65.32 26.975,65.075 ; 25.925,65.49 26.325,65.49 26.41,65.575 26.475,65.575 ; 25.925,68.83 26.076,68.83 26.321,69.075 26.475,69.075 ; 25.95,67.33 26.076,67.33 26.22,67.474 26.22,67.495 26.3,67.575 26.475,67.575 ; 25.975,65.66 26.21,65.66 26.375,65.825 26.725,65.825 26.975,65.575 ; 25.975,69.82 26.105,69.82 26.35,69.575 26.475,69.575 ; 25.98,70.33 26.316,70.33 26.73,70.33 26.975,70.575 ; 26,68.49 26.25,68.49 26.335,68.575 26.475,68.575 ; 26.025,69.99 26.175,69.99 26.34,69.825 26.725,69.825 26.975,69.575 ; 26.025,72.9 26.225,72.7 26.225,72.45 26.475,72.2 26.475,72.075 ; 26.075,70.16 26.246,70.16 26.331,70.075 26.475,70.075 ; 26.175,67.16 26.214,67.16 26.374,67.32 26.72,67.32 26.975,67.575 ; 26.175,73.05 26.475,72.75 26.475,72.575 ; 26.225,63.075 26.225,63.7 26.475,63.95 26.475,64.075 ; 26.299,68.745 26.374,68.82 26.576,68.82 26.72,68.676 26.72,68.625 26.77,68.575 26.975,68.575 ; 26.475,63.2 26.475,63.575 ; 26.55,73 26.725,72.825 26.725,72.325 26.975,72.075 ; 26.73,63.23 26.73,63.83 26.975,64.075 ; 26.85,73.025 26.975,72.9 26.975,72.575 ; 26.975,63.2 26.975,63.575 ; 26.975,66.075 27.3,66.4 v1@27.425,66.4 ; 26.98,71.075 27.055,71.15 v1(27.4,71.15) ; 27.075,73.1 27.225,72.95 27.225,72.325 27.475,72.075 ; 27.225,63.2 27.225,63.825 27.475,64.075 ; 27.3,73.175 27.475,73 27.475,72.575 ; v1(27.35,69.4) 27.425,69.325 27.925,69.325 ; v1@27.375,64.975 27.4,64.975 27.475,64.9 27.475,64.575 27.475,64.63 ; v1@27.4,67.875 27.425,67.9 27.8,67.9 27.925,68.025 ; v1@27.45,69 27.475,69.025 28.275,69.025 28.575,69.325 ; 27.475,62.925 27.475,63.575 ; 27.475,71.575 27.72,71.82 27.72,72.775 27.65,72.845 27.65,73.1 27.525,73.225 ; v1@27.5,65.525 27.55,65.475 27.875,65.475 27.925,65.425 ; 27.73,63.055 27.73,63.83 27.975,64.075 ; 27.87,69.325 27.9,69.35 ; v1(27.9,71.15) 27.9,70.65 27.925,70.625 ; v1(27.9,74.375) 27.96,74.315 27.96,73.412 28,73.372 28,73.025 28,72.988 28.06,72.928 28.06,72.615 28.06,72.34 ; 27.925,66.075 27.925,66.05 v1@28.238,65.737 ; 27.925,69.975 v1@28.263,69.638 ; 27.975,64.575 v1@27.975,65 ; 27.975,71.575 28.22,71.82 28.22,72.176 28.22,72.18 28.06,72.34 ; 28.06,72.35 28.06,72.34 ; 28.225,63.45 28.225,64.325 28.475,64.575 ; 28.395,63.525 28.395,63.9 28.475,63.98 28.475,64.075 ; v1(28.4,71.15) 28.4,71.495 28.475,71.57 ; v1(28.45,65) 28.45,65.275 28.575,65.4 28.575,65.425 ; 28.575,69.975 28.85,69.7 v1@28.85,69.625 ; 28.632,63.818 28.725,63.912 28.725,64.325 28.975,64.575 ; 28.73,63.525 28.73,63.676 28.802,63.748 28.975,63.921 28.975,64.075 ; v1@28.875,65.75 29.725,65.75 29.855,65.62 29.855,65.445 29.875,65.425 ; v1(28.875,74) 29.05,73.825 29.05,72.825 28.975,72.75 28.975,72.575 ; 28.975,63.15 28.975,63.575 ; 29.225,63.425 29.225,63.825 29.475,64.075 ; 29.475,63.2 29.475,63.575 ; 29.475,64.575 29.72,64.33 29.72,63.58 ; v1@29.55,70.3 29.875,69.975 ; 29.73,74.3 29.73,72.32 29.975,72.075 ; 29.89,63.675 29.89,63.99 29.975,64.075 ; 29.975,72.575 29.975,74.325 ; 30.06,63.625 30.06,63.747 30.23,63.917 30.23,64.33 30.475,64.575 ; 30.225,74.225 30.225,72.325 30.475,72.075 ; 30.3,63.1 30.3,63.404 30.23,63.474 30.23,63.676 30.475,63.921 30.475,64.075 ; v1(30.3,71.15) 30.3,70.85 30.475,70.675 ; 30.475,63.075 30.475,63.575 ; 30.475,72.575 30.475,74.175 ; 30.725,63.125 30.725,63.825 30.975,64.075 ; 30.89,72.925 30.89,72.16 30.975,72.075 ; 30.975,63.15 30.975,63.575 ; 30.975,71.575 31.22,71.33 31.576,71.33 31.72,71.474 31.72,71.72 31.75,71.75 31.825,71.825 31.97,71.825 32.071,71.825 32.225,71.979 32.225,73.775 ; 31.075,72.388 31.075,72.325 31.225,72.175 31.225,71.825 31.475,71.575 ; 31.22,63.474 31.22,64.32 31.475,64.575 ; 31.23,72.65 31.23,72.474 31.475,72.229 31.475,72.075 ; 31.39,63.6 31.39,63.99 31.475,64.075 ; 31.475,72.575 31.475,73.775 ; 31.764,63.711 31.975,63.921 31.975,64.075 ; 32.23,63.055 32.23,63.83 32.475,64.075 ; 32.475,63.05 32.475,63.575 ; 32.475,72.075 32.475,73.65 ; 32.725,73.4 32.725,71.825 32.975,71.575 ; 32.89,63.55 32.89,63.821 32.975,63.906 32.975,64.075 ; 33,64.575 32.975,64.575 33.2,64.35 33.22,64.33 33.22,63.91 33.06,63.75 33.06,63.55 ; 33.23,63.28 33.23,63.68 33.475,63.925 33.475,64.075 ; 33.475,64.575 33.72,64.33 33.72,63.97 33.72,61.975
  Top Layer w0.1: 31.725,73.725 31.725,72.325 31.975,72.075 ; 31.975,72.575 31.975,73.7 ; 32.975,72.075 32.975,72.225 33.075,72.325 33.225,72.475 33.225,73.475 ; 32.975,72.575 32.975,73.1 ; 33.475,72.575 33.475,73.38
  Top Layer w0.12: 33.72,61.975 33.72,61.305 36.925,58.1 36.925,56.55
  Bottom Layer w0.09: 24.55,68.5 26.725,68.5 27.4,67.825 v1@27.4,67.8 ; 26.225,69.75 26.825,69.75 27.175,69.4 v1@27.4,69.4 ; 26.3,69.4 26.725,69.4 27.175,68.95 27.35,68.95 v1@27.425,68.875 ; 26.65,71.9 v1(27.4,71.15) ; 26.75,66.4 v1(27.4,66.4) ; 26.875,65.5 v1(27.475,65.5) ; 27.175,70.25 27.538,70.25 28.138,69.65 v1(28.2,69.65) ; 27.257,66.055 27.92,66.055 v1@28.225,65.75 ; 27.275,65.85 27.613,65.85 27.781,65.681 28.088,65.375 28.5,65.375 v1@28.875,65.75 ; v1@27.3,68 v1@27.5,68 ; 27.325,70.5 27.55,70.5 28.05,70 28.3,70 28.55,70 v1@28.9,69.65 ; 27.4,63.55 v1(27.4,65) ; 27.55,70.75 27.8,70.75 v1(28.2,70.35) ; 27.575,71.975 27.9,71.65 v1(27.9,71.15) ; 27.95,63.425 v1(27.95,65) ; 28.25,63.45 28.25,64.8 v1(28.45,65) ; v1(28.4,71.15) 28.4,72.1 ; 29.025,71.7 29.025,71.475 28.95,71.4 28.95,70.9 v1@29.575,70.275 ; 30.095,72.4 30.095,71.38 v1@30.3,71.175
  Bottom Layer w0.1: 26.025,65.675 26.75,66.4 ; 31.8,63.35 31.975,63.525 v1(31.975,65)
  other v1: 32.975,65 28.2,65.75 28.85,65.8 27.4,67.9 27.4,68.9 28.85,69.65 29.5,70.35

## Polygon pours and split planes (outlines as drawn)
5V_VIN on Signal Layer 2 "5V_VIN" (solid, remove dead copper, pour order 94): 12.675,88.875 12.675,88.1 9.35,88.1 9.325,88.075 9.319,87 9.328,80.375 18.55,80.375 19.325,81.15 19.325,83.25 17.25,83.25 17.25,88.875
VDD_DDR on Signal Layer 2 "VDD_DDR" (solid, remove dead copper, pour order 81): 8.123,90.527 8.123,87.359 9.534,87.359 9.825,87.65 12.475,91.15 14.125,92.8 27.2,92.8 32.243,87.757 32.225,80.925 32.25,80.9 32.25,55.125 61.45,55.125 61.45,80.9 36.45,80.9 36.45,89.675 30.55,95.575 11.475,95.575 8.123,92.223 8.123,90.6
VDD on Signal Layer 2 "VDD" (solid, remove dead copper, pour order 86): 14.985,77.625 24.393,63.925 30.539,63.925 30.539,66.825 30.414,66.95 29.489,67.875 23.928,69.432 17.27,77.625
VDD_CORE on Signal Layer 2 "VDD_CORE" (solid, remove dead copper, pour order 88): 26.225,84.05 20.8,89.475 16.125,89.475 16.125,92.45 26.325,92.45 29.375,89.4 31.75,87.024 31.75,65.575 30.396,65.575 30.396,67.08 29.319,68.059 29.153,68.209 26.225,68.209
GND on Signal Layer 2 "GND_L2" (solid, pour order 140): 0.4,119.6 85.575,119.6 85.575,0.425 0.4,0.425
5V_VIN on Top Layer "5V_VIN" (solid, remove dead copper, pour order 122): 10.825,88.7 10.725,88.8 9.925,88.8 9.825,88.7 9.825,87.925 11.15,86.6 12.125,86.6 12.225,86.7 12.225,87.5 11.925,87.8 11.325,87.8 10.825,88.3
NetL2_1 on Top Layer "NetL2_1" (solid, remove dead copper, pour order 119): 12.625,88.5 12.625,87.8 12.6,87.775 12.425,87.775 12.1,88.1 11.425,88.1 11.025,88.5 11.025,89.9 11.225,90.1 12.825,90.1 13.025,89.9 13.025,88.9
5V_VIN on Top Layer "5V_VIN" (solid, remove dead copper, pour order 106): 13.225,89.6 13.125,89.5 13.125,88.6 13.425,88.3 13.725,88.3 14.225,88.8 14.225,89.6
NetL1_1 on Top Layer "NetL1_1" (solid, remove dead copper, pour order 115): 16.375,89.9 14.425,89.9 14.425,88.8 14.025,88.4 14.025,88.1 14.125,88 14.525,88 15.325,88.8 16.225,88.8 16.375,88.95
5V_VIN on Top Layer "5V_VIN" (solid, remove dead copper, pour order 104): 10.825,79.4 9.925,79.4 9.825,79.5 9.825,80.3 11.125,81.6 12.325,81.6 12.425,81.7 12.425,82.5 12.625,82.5 12.625,81.2 12.525,81.1 12.125,80.7 11.325,80.7 10.975,80.35 10.975,79.6
NetL4_1 on Top Layer "NetL4_1" (solid, remove dead copper, pour order 114): 12.825,81.2 12.825,82.5 13.025,82.5 13.025,79.6 12.725,79.3 11.225,79.3 11.125,79.4 11.125,80.3 11.425,80.6 12.225,80.6
NetL3_1 on Top Layer "NetL3_1" (solid, remove dead copper, pour order 116): 14.425,82.5 14.625,82.5 14.625,81.3 14.725,81.2 14.925,81.2 15.525,80.6 16.025,80.6 16.4,80.225 16.4,79.575 16.125,79.3 14.425,79.3 14.425,80.4
5V_VIN on Top Layer "NetC47_2" (solid, remove dead copper, pour order 117): 14.025,82.5 14.025,81.6 13.725,81.3 13.725,80.7 13.425,80.4 13.225,80.4 13.125,80.3 13.125,79.8 13.225,79.7 14.125,79.7 14.225,79.8 14.225,80.4 14.325,80.5 14.325,82.4 14.225,82.5
GND on Top Layer "GND_L01_P138" (solid, remove dead copper, pour order 138): 0.35,119.45 0.35,0.775 85.65,0.775 85.65,119.45
GND on Signal Layer 1 "GND" (solid, remove dead copper, pour order 96): 0.408,119.592 85.592,119.592 85.592,0.408 0.408,0.408
GND on Bottom Layer "GND_L04_P098" (solid, remove dead copper, pour order 98): 86,120 0,120 0,0.425 86,0.425

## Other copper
Top Layer:
  pour cut-out: 11.825,82.5 11.825,86.6 16.825,86.6 16.825,82.5
  pour cut-out: 33.175,76.5 64.275,76.5 64.275,53.725 33.175,53.725
Bottom Layer:
  pour cut-out: 33.675,49.4 62.35,49.4 62.75,49.4 63.775,49.4 63.775,50.225 63.775,82.425 33.675,82.425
